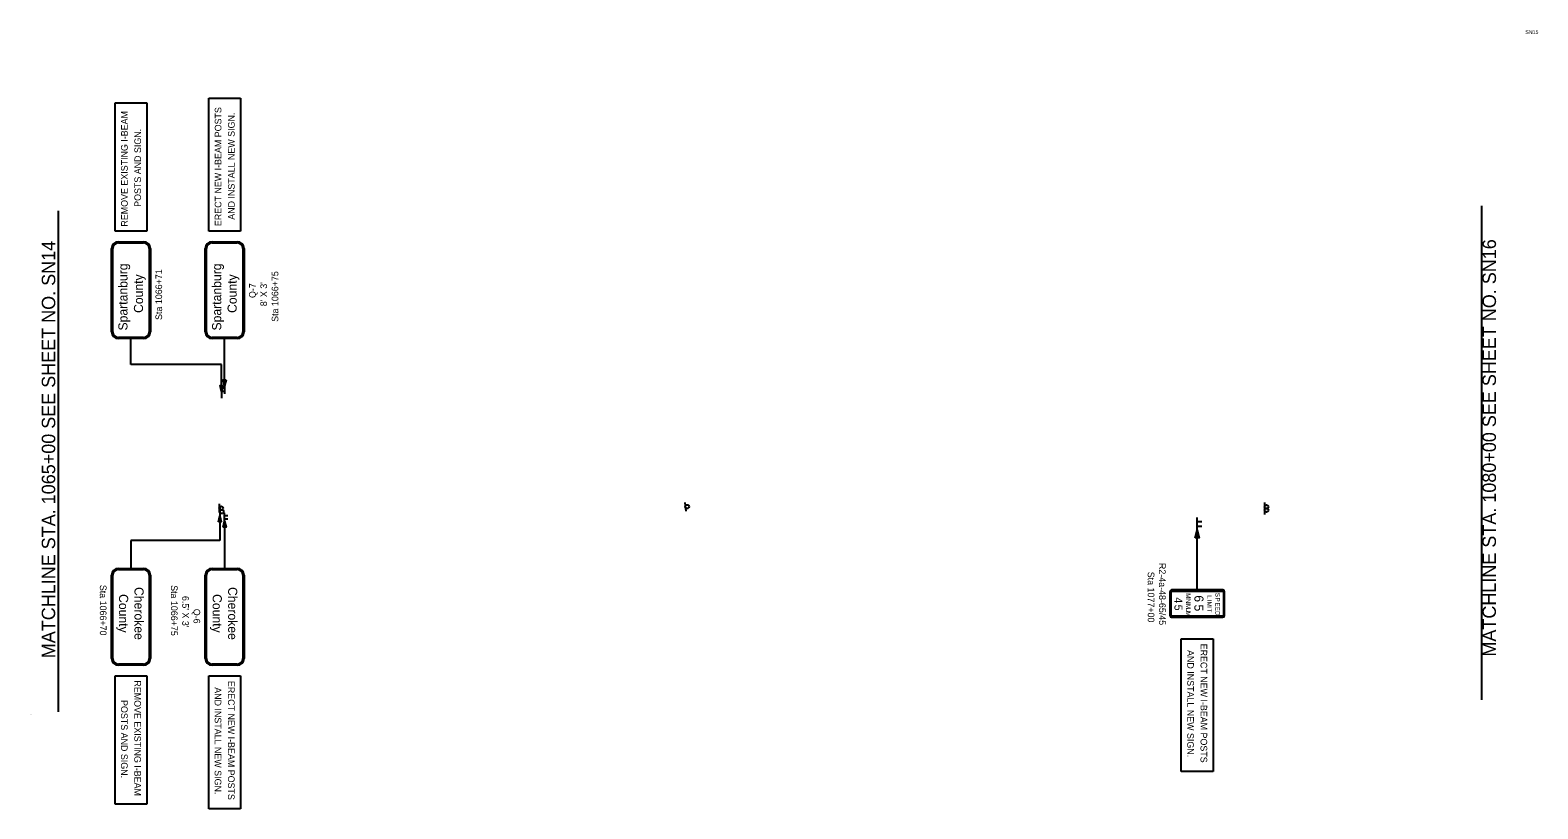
# Model space of a CAD drawing. Extents: x 1738714 to 1740303, y 1165670 to 1166490.
import ezdxf

# ---------------------------------------------------------------- set-up
doc = ezdxf.new("R2010")
doc.units = 0
for name, color, linetype in [('Default', 7, 'Continuous'), ('RD_SHT_MatchLine', 7, 'Continuous'), ('RD_SHT_TX', 7, 'Continuous'), ('SN_P_Signs', 7, 'Continuous')]:
    doc.layers.add(name, color=color, linetype=linetype)

msp = doc.modelspace()

# ---------------------------------------------------------------- linework, layer by layer
at = {"layer": 'RD_SHT_MatchLine'}
for points in [[(1740243.7, 1165784.3), (1740243.7, 1166044), (1740243.7, 1166305)], [(1738743.7, 1165771.7), (1738743.7, 1166044), (1738743.7, 1166299.6)]]:
    msp.add_lwpolyline(points, dxfattribs=at)
at = {"layer": 'SN_P_Signs'}
for p, q in [((1738803.2, 1166278.4), (1738803.2, 1166413.4)), ((1738803.2, 1166413.4), (1738836.8, 1166413.4)), ((1738836.8, 1166413.4), (1738836.8, 1166278.4)), ((1738901.9, 1166278.4), (1738901.9, 1166418.4)), ((1738901.9, 1166418.4), (1738935.5, 1166418.4)), ((1738935.5, 1166418.4), (1738935.5, 1166278.4)), ((1738836.8, 1166278.4), (1738803.2, 1166278.4)), ((1738935.5, 1166278.4), (1738901.9, 1166278.4)), ((1738799.6, 1166172.3), (1738799.6, 1166259.9)), ((1738898.3, 1166172.3), (1738898.3, 1166259.9)), ((1738820, 1166137.7), (1738820, 1166165.1)), ((1738918.7, 1166115.4), (1738918.7, 1166165.1)), ((1738915.4, 1166137.7), (1738820, 1166137.7)), ((1738915.4, 1166109.4), (1738915.4, 1166137.7)), ((1738918.7, 1166112.8), (1738915.4, 1166112.8)), ((1738915.9, 1166102.2), (1738915.6, 1166110.1)), ((1738918.7, 1166115.4), (1738918.7, 1166106.7)), ((1738918.7, 1166109.4), (1738915.4, 1166109.4)), ((1738913, 1165990.9), (1738913, 1165981.9)), ((1738913.6, 1165987.3), (1738913.6, 1165978.3)), ((1739403.8, 1165992.4), (1739404.6, 1165983.4)), ((1740014.7, 1165992.3), (1740014.7, 1165983.3)), ((1740014.7, 1165988.8), (1740014.7, 1165979.8)), ((1738913.6, 1165978.3), (1738913.6, 1165952.5)), ((1738918.7, 1165972.7), (1738918.7, 1165981.4)), ((1738918.7, 1165978.6), (1738922.1, 1165978.6)), ((1738918.7, 1165975.3), (1738922.1, 1165975.3)), ((1738918.7, 1165972.7), (1738918.7, 1165922.9)), ((1739943.7, 1165963.5), (1739943.7, 1165976.6)), ((1739943.7, 1165972.4), (1739948.7, 1165972.4)), ((1739943.7, 1165967.4), (1739948.7, 1165967.4)), ((1738820, 1165952.5), (1738820, 1165922.9)), ((1738913.6, 1165952.5), (1738820, 1165952.5)), ((1739943.7, 1165900.2), (1739943.7, 1165963.5)), ((1738840.5, 1165915.7), (1738840.5, 1165828.1)), ((1738939.2, 1165915.7), (1738939.2, 1165828.1)), ((1739914.9, 1165898.4), (1739914.9, 1165873.2)), ((1739970.7, 1165900.2), (1739916.7, 1165900.2)), ((1739972.5, 1165873.2), (1739972.5, 1165898.4)), ((1739916.7, 1165871.4), (1739970.7, 1165871.4)), ((1739926.9, 1165708.8), (1739926.9, 1165848.9)), ((1739926.9, 1165848.9), (1739960.5, 1165848.9)), ((1739926.9, 1165708.8), (1739926.9, 1165848.9)), ((1739926.9, 1165848.9), (1739960.5, 1165848.9)), ((1739960.5, 1165848.9), (1739960.5, 1165708.8)), ((1739960.5, 1165848.9), (1739960.5, 1165708.8)), ((1738803.2, 1165674.6), (1738803.2, 1165809.6)), ((1738803.2, 1165809.6), (1738836.8, 1165809.6)), ((1738836.8, 1165809.6), (1738836.8, 1165674.6)), ((1738901.9, 1165669.6), (1738901.9, 1165809.6)), ((1738901.9, 1165809.6), (1738935.5, 1165809.6)), ((1738935.5, 1165809.6), (1738935.5, 1165669.6)), ((1739960.5, 1165708.8), (1739926.9, 1165708.8)), ((1739960.5, 1165708.8), (1739926.9, 1165708.8)), ((1738836.8, 1165674.6), (1738803.2, 1165674.6)), ((1738935.5, 1165669.6), (1738901.9, 1165669.6))]:
    msp.add_line(p, q, dxfattribs=at)
for points in [[(1738800.8, 1166172.3), (1738800.8, 1166259.9)], [(1738806.8, 1166267.1), (1738833.3, 1166267.1)], [(1738806.8, 1166265.9), (1738833.3, 1166265.9)], [(1738839.3, 1166259.9), (1738839.3, 1166172.3)], [(1738840.5, 1166259.9), (1738840.5, 1166172.3)], [(1738899.5, 1166172.3), (1738899.5, 1166259.9)], [(1738905.5, 1166267.1), (1738932, 1166267.1)], [(1738905.5, 1166265.9), (1738932, 1166265.9)], [(1738938, 1166259.9), (1738938, 1166172.3)], [(1738939.2, 1166259.9), (1738939.2, 1166172.3)], [(1738833.3, 1166166.3), (1738806.8, 1166166.3)], [(1738833.3, 1166165.1), (1738806.8, 1166165.1)], [(1738932, 1166166.3), (1738905.5, 1166166.3)], [(1738932, 1166165.1), (1738905.5, 1166165.1)], [(1738806.8, 1165922.9), (1738833.3, 1165922.9)], [(1738806.8, 1165921.7), (1738833.3, 1165921.7)], [(1738905.5, 1165922.9), (1738932, 1165922.9)], [(1738905.5, 1165921.7), (1738932, 1165921.7)], [(1738799.6, 1165828.1), (1738799.6, 1165915.7)], [(1738800.8, 1165828.1), (1738800.8, 1165915.7)], [(1738839.3, 1165915.7), (1738839.3, 1165828.1)], [(1738898.3, 1165828.1), (1738898.3, 1165915.7)], [(1738899.5, 1165828.1), (1738899.5, 1165915.7)], [(1738938, 1165915.7), (1738938, 1165828.1)], [(1739915.4, 1165898.4), (1739915.4, 1165873.2)], [(1739916.1, 1165873.2), (1739916.1, 1165898.4)], [(1739970.7, 1165899.7), (1739916.7, 1165899.7)], [(1739916.7, 1165899), (1739970.7, 1165899)], [(1739971.3, 1165898.4), (1739971.3, 1165873.2)], [(1739972.1, 1165873.2), (1739972.1, 1165898.4)], [(1739970.7, 1165872.6), (1739916.7, 1165872.6)], [(1739916.7, 1165871.8), (1739970.7, 1165871.8)], [(1738833.3, 1165822.1), (1738806.8, 1165822.1)], [(1738833.3, 1165820.9), (1738806.8, 1165820.9)], [(1738932, 1165822.1), (1738905.5, 1165822.1)], [(1738932, 1165820.9), (1738905.5, 1165820.9)]]:
    msp.add_lwpolyline(points, dxfattribs=at)
for points in [[(1738916.9, 1166115.6), (1738915.4, 1166109.4), (1738913.9, 1166115.6)], [(1738920.3, 1166121.5), (1738918.7, 1166115.4), (1738917.2, 1166121.5)], [(1738912.1, 1165972.1), (1738913.6, 1165978.3), (1738915.2, 1165972.1)], [(1738917.2, 1165966.5), (1738918.7, 1165972.7), (1738920.3, 1165966.5)], [(1739941.7, 1165955.3), (1739943.7, 1165963.5), (1739945.8, 1165955.3)]]:
    msp.add_lwpolyline(points, close=True, dxfattribs=at)
for centre in [(1738915, 1165986.4), (1738915.6, 1165982.8), (1739406.2, 1165988), (1740016.7, 1165987.8), (1740016.7, 1165984.3)]:
    msp.add_circle(centre, 2, dxfattribs=at)
for centre, radius, start, end in [((1738806.8, 1166259.9), 7.2, 90, 180), ((1738806.8, 1166259.9), 6, 90, 180), ((1738833.3, 1166259.9), 7.2, 0, 90), ((1738833.3, 1166259.9), 6, 0, 90), ((1738905.5, 1166259.9), 7.2, 90, 180), ((1738905.5, 1166259.9), 6, 90, 180), ((1738932, 1166259.9), 7.2, 0, 90), ((1738932, 1166259.9), 6, 0, 90), ((1738806.8, 1166172.3), 7.2, 180, 270), ((1738806.8, 1166172.3), 6, 180, 270), ((1738833.3, 1166172.3), 6, 270, 0), ((1738833.3, 1166172.3), 7.2, 270, 0), ((1738905.5, 1166172.3), 7.2, 180, 270), ((1738905.5, 1166172.3), 6, 180, 270), ((1738932, 1166172.3), 6, 270, 0), ((1738932, 1166172.3), 7.2, 270, 0), ((1738806.8, 1165915.7), 7.2, 90, 180), ((1738806.8, 1165915.7), 6, 90, 180), ((1738833.3, 1165915.7), 7.2, 0, 90), ((1738833.3, 1165915.7), 6, 0, 90), ((1738905.5, 1165915.7), 7.2, 90, 180), ((1738905.5, 1165915.7), 6, 90, 180), ((1738932, 1165915.7), 7.2, 0, 90), ((1738932, 1165915.7), 6, 0, 90), ((1739916.7, 1165898.4), 1.8, 90, 180), ((1739916.7, 1165898.4), 1.35, 90, 180), ((1739916.7, 1165898.4), 0.6, 90, 180), ((1739970.7, 1165898.4), 1.8, 0, 90), ((1739970.7, 1165898.4), 1.35, 0, 90), ((1739970.7, 1165898.4), 0.6, 0, 90), ((1739916.7, 1165873.2), 1.8, 180, 270), ((1739916.7, 1165873.2), 1.35, 180, 270), ((1739916.7, 1165873.2), 0.6, 180, 270), ((1739970.7, 1165873.2), 1.8, 270, 0), ((1739970.7, 1165873.2), 1.35, 270, 0), ((1739970.7, 1165873.2), 0.6, 270, 0), ((1738806.8, 1165828.1), 7.2, 180, 270), ((1738806.8, 1165828.1), 6, 180, 270), ((1738833.3, 1165828.1), 6, 270, 0), ((1738833.3, 1165828.1), 7.2, 270, 0), ((1738905.5, 1165828.1), 7.2, 180, 270), ((1738905.5, 1165828.1), 6, 180, 270), ((1738932, 1165828.1), 6, 270, 0), ((1738932, 1165828.1), 7.2, 270, 0)]:
    msp.add_arc(centre, radius, start, end, dxfattribs=at)

# ---------------------------------------------------------------- texts
at = {"layer": 'Default'}
for s, p in [('Sheet: 15', (1738713.7, 1165768.8)), ('Angle:  25.9453', (1738713.7, 1165768.6)), ('Align: A_I85', (1738713.7, 1165768.3))]:
    msp.add_text(s, height=0.208, dxfattribs=at).set_placement(p)
at = {"layer": 'RD_SHT_TX'}
msp.add_text('SN15', height=4, dxfattribs=at).set_placement((1740289.5, 1166486))
for s, p in [('MATCHLINE STA. 1080+00 SEE SHEET NO. SN16', (1740258.5, 1165830)), ('MATCHLINE STA. 1065+00 SEE SHEET NO. SN14', (1738740.1, 1165828.3))]:
    msp.add_text(s, height=14.173, rotation=89.9856, dxfattribs=at).set_placement(p)
at = {"layer": 'SN_P_Signs'}
for s, height, rotation, p in [('REMOVE EXISTING I-BEAM', 7, 90.0001, (1738816.6, 1166283.1)), ('ERECT NEW I-BEAM POSTS', 7, 90.0001, (1738915.3, 1166283.6)), ('AND INSTALL NEW SIGN.', 7, 90.0001, (1738929.3, 1166290.3)), ('POSTS AND SIGN.', 7, 90.0001, (1738830.6, 1166303.9)), ('Spartanburg', 9.6, 90, (1738816.3, 1166173.6)), ('Sta 1066+71', 7, 90.0001, (1738852.8, 1166184.7)), ('Spartanburg', 9.6, 90, (1738915.1, 1166173.6)), ('County', 9.6, 90, (1738832.7, 1166192.1)), ('County', 9.6, 90, (1738931.4, 1166192.1)), ('Q-7', 7, 90.0001, (1738951.5, 1166207.8)), ("8' X 3'", 7, 90.0001, (1738963.4, 1166199.2)), ('Sta 1066+75', 7, 90.0001, (1738975.3, 1166182.7)), ('R2-4a-48-65/45', 7, 270.0001, (1739903.5, 1165928.7)), ('Sta 1066+70', 7, 270.0001, (1738787.2, 1165905.6)), ('Sta 1066+75', 7, 270.0001, (1738862.1, 1165905.3)), ('Sta 1077+00', 7, 270.0001, (1739891.6, 1165919.4)), ('County', 9.6, 270, (1738807.4, 1165895.9)), ('Cherokee', 9.6, 270, (1738823.7, 1165903.3)), ("6.5' X 3'", 7, 270.0001, (1738874, 1165893.9)), ('County', 9.6, 270, (1738906.1, 1165895.9)), ('Cherokee', 9.6, 270, (1738922.4, 1165903.3)), ('4', 8.4, 270, (1739919.7, 1165892.5)), ('M', 4.8, 270, (1739932, 1165896.8)), ('I', 4.8, 270, (1739932, 1165892.7)), ('N', 4.8, 270, (1739932, 1165891)), ('6', 9.6, 270, (1739940.7, 1165894.6)), ('L', 4.8, 270, (1739954.2, 1165894.6)), ('I', 4.8, 270, (1739954.2, 1165890.1)), ('M', 4.8, 270, (1739954.2, 1165888)), ('S', 4.8, 270, (1739962.9, 1165897.3)), ('P', 4.8, 270, (1739962.9, 1165892.2)), ('Q-6', 7, 270.0001, (1738885.9, 1165880.4)), ('5', 8.4, 270, (1739919.7, 1165884.7)), ('I', 4.8, 270, (1739932, 1165887.3)), ('M', 4.8, 270, (1739932, 1165885.6)), ('U', 4.8, 270, (1739932, 1165881.5)), ('M', 4.8, 270, (1739932, 1165877.9)), ('5', 9.6, 270, (1739940.7, 1165884.9)), ('I', 4.8, 270, (1739954.2, 1165882.3)), ('T', 4.8, 270, (1739954.2, 1165880.5)), ('E', 4.8, 270, (1739962.9, 1165887.1)), ('E', 4.8, 270, (1739962.9, 1165882.6)), ('D', 4.8, 270, (1739962.9, 1165878)), ('ERECT NEW I-BEAM POSTS', 7, 270.0001, (1739947.2, 1165843.6)), ('ERECT NEW I-BEAM POSTS', 7, 270.0001, (1739947.2, 1165843.6)), ('AND INSTALL NEW SIGN.', 7, 270.0001, (1739933.2, 1165836.9)), ('AND INSTALL NEW SIGN.', 7, 270.0001, (1739933.2, 1165836.9)), ('REMOVE EXISTING I-BEAM', 7, 270.0001, (1738823.5, 1165804.9)), ('AND INSTALL NEW SIGN.', 7, 270.0001, (1738908.2, 1165797.7)), ('ERECT NEW I-BEAM POSTS', 7, 270.0001, (1738922.2, 1165804.4)), ('POSTS AND SIGN.', 7, 270.0001, (1738809.5, 1165784.2))]:
    msp.add_text(s, height=height, rotation=rotation, dxfattribs=at).set_placement(p)

doc.saveas('drawing.dxf')
